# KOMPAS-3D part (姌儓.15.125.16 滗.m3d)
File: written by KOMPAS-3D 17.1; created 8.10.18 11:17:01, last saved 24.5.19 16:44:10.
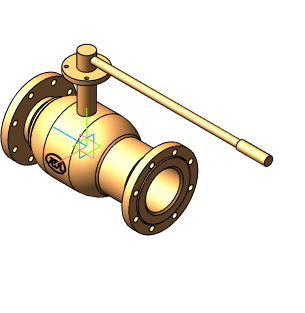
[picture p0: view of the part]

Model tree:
1. Операция без истории:2  (labels: Сталь 20  ГОСТ 1050-2013)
